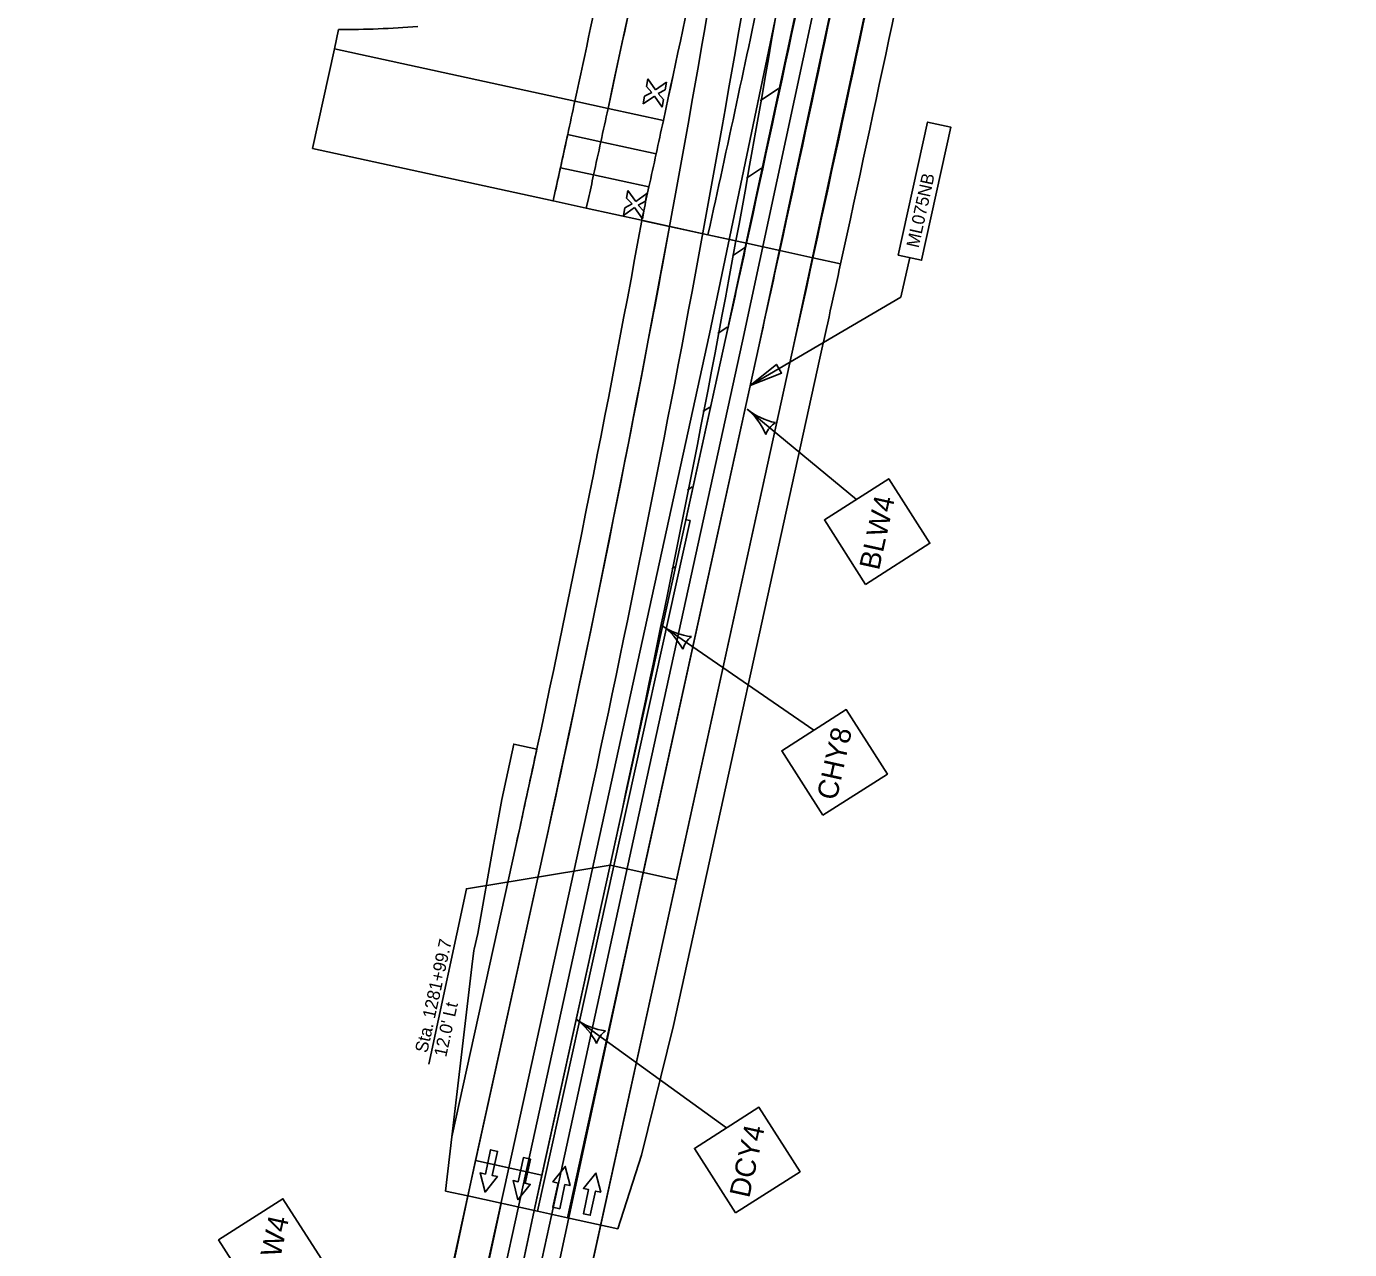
# Model space of a CAD drawing. Extents: x 14104283 to 14120882, y 8635219 to 8671666.
# Drawn here: x 14107625.7 to 14108093.2, y 8639045.1 to 8639477.1 of the extents above; entities that cross this region are included whole.
import ezdxf

# ---------------------------------------------------------------- set-up
doc = ezdxf.new("R2010")
doc.units = 0
for name, color, linetype in [('Cell', 7, 'Continuous'), ('dsnPaintExistingBrokenLaneLineWhite', 7, 'Continuous'), ('dsnPaintExistingEdgeLineRightWhite', 7, 'Continuous'), ('dsnPaintPlaceBrokenLaneWhite', 7, 'Continuous'), ('dsnPaintPlaceChannelizingLaneYellow', 7, 'Continuous'), ('dsnPaintPlaceDoubleCenterLineYellow', 7, 'Continuous'), ('dsnPaintPlaceEdgeLineRightWhite', 7, 'Continuous'), ('dsnPaintRemoveDoubleCenterLineYellow', 7, 'Continuous'), ('dsnPaintRemoveEdgeLineWhite', 7, 'Continuous'), ('dsnPaintRemoveEdgeLineYellow', 7, 'Continuous'), ('dsnShadingPaved', 7, 'Continuous'), ('dsnStdLabel', 7, 'Continuous'), ('dsnStgShadingPrevPav', 7, 'Continuous'), ('Text', 7, 'Continuous')]:
    doc.layers.add(name, color=color, linetype=linetype)

msp = doc.modelspace()

# ---------------------------------------------------------------- linework, layer by layer
at = {"layer": 'Cell'}
for p, q in [((14107845.2, 8639458.65), (14107844.72, 8639455.94)), ((14107847.94, 8639454.75), (14107845.2, 8639458.65)), ((14107851.85, 8639457.49), (14107847.94, 8639454.75)), ((14107851.37, 8639454.78), (14107851.85, 8639457.49)), ((14107843.65, 8639449.78), (14107847.55, 8639452.53)), ((14107844.12, 8639452.49), (14107843.65, 8639449.78)), ((14107846.64, 8639453.83), (14107844.12, 8639452.49)), ((14107844.72, 8639455.94), (14107846.64, 8639453.83)), ((14107847.55, 8639452.53), (14107850.3, 8639448.62)), ((14107848.86, 8639453.44), (14107851.37, 8639454.78)), ((14107850.77, 8639451.33), (14107848.86, 8639453.44)), ((14107850.3, 8639448.62), (14107850.77, 8639451.33)), ((14107838.22, 8639419.23), (14107837.75, 8639416.52)), ((14107837.75, 8639416.52), (14107839.66, 8639414.41)), ((14107840.97, 8639415.32), (14107838.22, 8639419.23)), ((14107844.87, 8639418.07), (14107840.97, 8639415.32)), ((14107841.88, 8639414.02), (14107844.4, 8639415.36)), ((14107844.4, 8639415.36), (14107844.87, 8639418.07)), ((14107836.67, 8639410.36), (14107840.58, 8639413.11)), ((14107837.15, 8639413.07), (14107836.67, 8639410.36)), ((14107839.66, 8639414.41), (14107837.15, 8639413.07)), ((14107840.58, 8639413.11), (14107843.32, 8639409.2)), ((14107843.8, 8639411.91), (14107841.88, 8639414.02)), ((14107843.32, 8639409.2), (14107843.8, 8639411.91))]:
    msp.add_line(p, q, dxfattribs=at)
for points in [[(14107789.7, 8639080.29), (14107792.14, 8639079.75), (14107790.27, 8639071.21), (14107792.11, 8639070.81), (14107787.72, 8639065.37), (14107786, 8639072.14), (14107787.83, 8639071.74)], [(14107801.31, 8639077.56), (14107803.75, 8639077.03), (14107801.89, 8639068.48), (14107803.72, 8639068.08), (14107799.34, 8639062.64), (14107797.61, 8639069.41), (14107799.45, 8639069.01)], [(14107814.11, 8639059.49), (14107811.66, 8639060.03), (14107813.53, 8639068.57), (14107811.7, 8639068.97), (14107816.08, 8639074.41), (14107817.8, 8639067.64), (14107815.97, 8639068.04)], [(14107824.92, 8639057.15), (14107822.48, 8639057.69), (14107824.34, 8639066.24), (14107822.51, 8639066.64), (14107826.89, 8639072.08), (14107828.62, 8639065.3), (14107826.78, 8639065.7)]]:
    msp.add_lwpolyline(points, close=True, dxfattribs=at)
for points in [[(14107787.83, 8639071.74), (14107786, 8639072.14), (14107787.72, 8639065.37), (14107792.11, 8639070.81), (14107790.27, 8639071.21), (14107792.14, 8639079.75), (14107789.7, 8639080.29), (14107787.83, 8639071.74)], [(14107799.45, 8639069.01), (14107797.61, 8639069.41), (14107799.34, 8639062.64), (14107803.72, 8639068.08), (14107801.89, 8639068.48), (14107803.75, 8639077.03), (14107801.31, 8639077.56), (14107799.45, 8639069.01)], [(14107815.97, 8639068.04), (14107817.8, 8639067.64), (14107816.08, 8639074.41), (14107811.7, 8639068.97), (14107813.53, 8639068.57), (14107811.66, 8639060.03), (14107814.11, 8639059.49), (14107815.97, 8639068.04)], [(14107826.78, 8639065.7), (14107828.62, 8639065.3), (14107826.89, 8639072.08), (14107822.51, 8639066.64), (14107824.34, 8639066.24), (14107822.48, 8639057.69), (14107824.92, 8639057.15), (14107826.78, 8639065.7)]]:
    msp.add_lwpolyline(points, dxfattribs=at)
at = {"layer": 'dsnPaintExistingBrokenLaneLineWhite'}
msp.add_line((14107796.13, 8639073.89), (14107820.2, 8639183.44), dxfattribs=at)
msp.add_arc((14101471.58, 8640578.08), 6500, 347.610212, 351.325989, dxfattribs=at)
at = {"layer": 'dsnPaintExistingEdgeLineRightWhite'}
for p, q in [((14107808.47, 8639186.01), (14107781.67, 8639064.01)), ((14107781.67, 8639064.01), (14107752.01, 8638929.68))]:
    msp.add_line(p, q, dxfattribs=at)
msp.add_arc((14101471.58, 8640578.08), 6488, 347.610212, 351.325989, dxfattribs=at)
at = {"layer": 'dsnPaintPlaceBrokenLaneWhite'}
for p, q in [((14107786.39, 8638912.75), (14107843.64, 8639178.29)), ((14107762.69, 8638916.73), (14107793.38, 8639061.35))]:
    msp.add_line(p, q, dxfattribs=at)
msp.add_lwpolyline([(14107843.64, 8639178.31), (14107884.58, 8639364.68), (14107924.33, 8639550.14), (14107962.2, 8639735.99), (14107989.47, 8639873.39), (14108016.73, 8640010.79)], dxfattribs=at)
at = {"layer": 'dsnPaintPlaceChannelizingLaneYellow'}
for p, q in [((14107891.4, 8639455.15), (14107884.98, 8639450.86)), ((14107885.38, 8639427.06), (14107880.12, 8639423.54)), ((14107879.35, 8639398.97), (14107875.12, 8639396.14)), ((14107873.33, 8639370.88), (14107869.98, 8639368.64)), ((14107867.16, 8639342.69), (14107864.7, 8639341.05)), ((14107860.96, 8639314.49), (14107859.28, 8639313.36)), ((14107854.77, 8639286.28), (14107853.72, 8639285.58))]:
    msp.add_line(p, q, dxfattribs=at)
msp.add_lwpolyline([(14107831.92, 8639180.86), (14107872.85, 8639367.2), (14107898.55, 8639487.12)], dxfattribs=at)
for start, end in [(349.4681, 351.325989), (347.610212, 349.4681)]:
    msp.add_arc((14101471.58, 8640578.08), 6512, start, end, dxfattribs=at)
at = {"layer": 'dsnPaintPlaceDoubleCenterLineYellow'}
for p in [(14107831.92, 8639180.86), (14107774.43, 8638914.24)]:
    msp.add_line(p, (14107805.11, 8639058.86), dxfattribs=at)
at = {"layer": 'dsnPaintPlaceEdgeLineRightWhite'}
msp.add_line((14107772.93, 8638800.49), (14107896.3, 8639362.11), dxfattribs=at)
msp.add_arc((14089678.7, 8643364.11), 18652, 347.610212, 348.776036, dxfattribs=at)
at = {"layer": 'dsnPaintRemoveDoubleCenterLineYellow'}
msp.add_line((14107796.13, 8639073.89), (14107763.69, 8638926.99), dxfattribs=at)
at = {"layer": 'dsnPaintRemoveEdgeLineWhite'}
msp.add_line((14107757.07, 8638810.81), (14107811.17, 8639057.08), dxfattribs=at)
msp.add_lwpolyline([(14107811.17, 8639057.08), (14107844.94, 8639211.53), (14107878.72, 8639365.97), (14107918.46, 8639551.34), (14107956.3, 8639737.1), (14108010.84, 8640011.94), (14108059.95, 8640246.87), (14108093.19, 8640398.18)], dxfattribs=at)
at = {"layer": 'dsnPaintRemoveEdgeLineYellow'}
msp.add_line((14107745.31, 8638813.23), (14107799.44, 8639059.65), dxfattribs=at)
msp.add_lwpolyline([(14107799.44, 8639059.65), (14107867, 8639368.55), (14107944.53, 8639739.44), (14107999.07, 8640014.27), (14108048.23, 8640249.45), (14108081.5, 8640400.87)], dxfattribs=at)
at = {"layer": 'dsnShadingPaved'}
for p, q in [((14107784.41, 8639076.47), (14107808.47, 8639186.01)), ((14107820.2, 8639183.44), (14107796.13, 8639073.89)), ((14107796.13, 8639073.89), (14107820.2, 8639183.44)), ((14107831.92, 8639180.86), (14107807.85, 8639071.32)), ((14107855.36, 8639175.71), (14107831.92, 8639180.86)), ((14107781.65, 8639063.92), (14107784.41, 8639076.47)), ((14107796.13, 8639073.89), (14107784.41, 8639076.47)), ((14107784.41, 8639076.47), (14107807.85, 8639071.32)), ((14107807.85, 8639071.32), (14107796.13, 8639073.89)), ((14107807.85, 8639071.32), (14107805.11, 8639058.86)), ((14107750.96, 8638919.22), (14107781.65, 8639063.92)), ((14107805.11, 8639058.86), (14107774.43, 8638914.24))]:
    msp.add_line(p, q, dxfattribs=at)
for points in [[(14107831.92, 8639180.86), (14107872.85, 8639367.2), (14107912.58, 8639552.57), (14107950.43, 8639738.33), (14108004.96, 8640013.11)], [(14108028.5, 8640008.43), (14107973.96, 8639733.6), (14107936.08, 8639547.66), (14107896.3, 8639362.11), (14107855.36, 8639175.71)]]:
    msp.add_lwpolyline(points, dxfattribs=at)
msp.add_lwpolyline([(14107649.12, 8638235.55), (14107625.69, 8638240.73), (14107678.53, 8638479.98), (14107744.48, 8638778.62), (14107774.43, 8638914.24), (14107805.11, 8639058.86), (14107831.92, 8639180.86), (14107855.36, 8639175.71), (14107834.62, 8639081.3), (14107772.93, 8638800.49), (14107710.93, 8638518.28), (14107648.94, 8638236.07)], close=True, dxfattribs=at)
for radius, start, end in [(6488, 347.610212, 351.325989), (6500, 347.610212, 351.325989), (6500, 347.610212, 351.325989), (6512, 349.4681, 351.325989), (6512, 347.610212, 349.4681)]:
    msp.add_arc((14101471.58, 8640578.08), radius, start, end, dxfattribs=at)
at = {"layer": 'dsnStdLabel'}
for p, q in [((14107919.02, 8639310.05), (14107880.3, 8639341.96)), ((14107903.96, 8639228.52), (14107850.2, 8639265.48)), ((14107873.1, 8639088.04), (14107819.95, 8639126.4))]:
    msp.add_line(p, q, dxfattribs=at)
for points in [[(14107922.2, 8639280.03), (14107944.94, 8639294.58), (14107930.39, 8639317.33), (14107907.65, 8639302.78)], [(14107907.14, 8639198.51), (14107929.88, 8639213.05), (14107915.33, 8639235.8), (14107892.59, 8639221.25)], [(14107876.27, 8639058.02), (14107899.02, 8639072.57), (14107884.47, 8639095.32), (14107861.72, 8639080.77)], [(14107708.11, 8639025.7), (14107730.86, 8639040.25), (14107716.31, 8639063), (14107693.56, 8639048.45)]]:
    msp.add_lwpolyline(points, close=True, dxfattribs=at)
for centre, radius, start, end in [((14107865.71, 8639324.25), 22.95, 22.4366, 50.5079), ((14107894.9, 8639359.67), 22.95, 230.5078, 258.579), ((14107895.15, 8639329.72), 8.86, 122.7736, 158.2421), ((14107837.2, 8639246.56), 22.95, 27.4258, 55.4971), ((14107863.2, 8639284.39), 22.95, 235.4969, 263.5682), ((14107866.06, 8639254.58), 8.86, 127.7628, 163.2312), ((14107806.52, 8639107.79), 22.95, 26.1067, 54.178), ((14107833.38, 8639145.01), 22.95, 234.1779, 262.2491), ((14107835.55, 8639115.14), 8.86, 126.4437, 161.9122)]:
    msp.add_arc(centre, radius, start, end, dxfattribs=at)
at = {"layer": 'dsnStgShadingPrevPav'}
for p, q in [((14107819.46, 8639450.69), (14107831.19, 8639448.13)), ((14107831.19, 8639448.13), (14107819.46, 8639450.69)), ((14107831.19, 8639448.13), (14107850.73, 8639443.87)), ((14107850.74, 8639443.87), (14107831.2, 8639448.13)), ((14107828.65, 8639436.4), (14107816.92, 8639438.96)), ((14107816.92, 8639438.96), (14107828.65, 8639436.4)), ((14107828.65, 8639436.4), (14107848.19, 8639432.14)), ((14107848.19, 8639432.14), (14107828.65, 8639436.4)), ((14107826.09, 8639424.68), (14107814.36, 8639427.23)), ((14107814.36, 8639427.23), (14107826.09, 8639424.68)), ((14107826.09, 8639424.68), (14107845.63, 8639420.42)), ((14107845.63, 8639420.42), (14107826.09, 8639424.68)), ((14107843.14, 8639408.63), (14107852.92, 8639406.48)), ((14107866.49, 8639403.5), (14107852.92, 8639406.48)), ((14107880.14, 8639400.54), (14107866.49, 8639403.51)), ((14107866.49, 8639403.51), (14107866.49, 8639403.5)), ((14107891.87, 8639397.99), (14107880.14, 8639400.54)), ((14107891.86, 8639397.97), (14107880.14, 8639400.52)), ((14107891.86, 8639397.97), (14107903.59, 8639395.42)), ((14107891.86, 8639397.97), (14107903.59, 8639395.42)), ((14107903.59, 8639395.44), (14107913.36, 8639393.31)), ((14107903.59, 8639395.44), (14107913.36, 8639393.31)), ((14107816.84, 8639056.28), (14107884.58, 8639364.69)), ((14107816.84, 8639056.28), (14107884.58, 8639364.69)), ((14107858.72, 8639302.86), (14107872.86, 8639367.26)), ((14107872.86, 8639367.26), (14107858.72, 8639302.86)), ((14107906.07, 8639359.97), (14107854.27, 8639124.15)), ((14107860.16, 8639302.55), (14107858.72, 8639302.86)), ((14107858.81, 8639302.85), (14107860.17, 8639302.55)), ((14107806.3, 8639058.6), (14107860.16, 8639302.55)), ((14107860.17, 8639302.55), (14107806.31, 8639058.6)), ((14107808.47, 8639186.01), (14107781.67, 8639064.01)), ((14107854.27, 8639124.15), (14107843.05, 8639078.38)), ((14107843.05, 8639078.38), (14107834.68, 8639052.36)), ((14107781.67, 8639064.01), (14107806.3, 8639058.6)), ((14107806.31, 8639058.6), (14107816.84, 8639056.28)), ((14107834.68, 8639052.36), (14107816.84, 8639056.28))]:
    msp.add_line(p, q, dxfattribs=at)
for points in [[(14107819.46, 8639450.69), (14107734.48, 8639469.22), (14107735.97, 8639476.04)], [(14107812.54, 8639418.89), (14107811.79, 8639415.51), (14107726.81, 8639434.04), (14107734.48, 8639469.22), (14107819.46, 8639450.69)], [(14107824.26, 8639416.31), (14107823.51, 8639412.94), (14107811.79, 8639415.51), (14107812.54, 8639418.89)], [(14107843.79, 8639412.02), (14107843.05, 8639408.65), (14107823.51, 8639412.94), (14107824.26, 8639416.31)], [(14107867.23, 8639406.87), (14107866.49, 8639403.51), (14107876.38, 8639401.36), (14107866.49, 8639403.5), (14107843.05, 8639408.65), (14107843.79, 8639412.02)], [(14107867.23, 8639406.87), (14107866.49, 8639403.51), (14107880.14, 8639400.54)], [(14107798.71, 8639188.16), (14107776.02, 8639084.89), (14107783.02, 8639144.91), (14107783.81, 8639150.65), (14107783.9, 8639151.14), (14107785.2, 8639156.75), (14107790.77, 8639188.01), (14107791.75, 8639193.68), (14107793.6, 8639204.06), (14107797.89, 8639223.6), (14107806.01, 8639221.81)], [(14107808.47, 8639186.01), (14107781.67, 8639064.01), (14107773.79, 8639065.74), (14107776.02, 8639084.89), (14107798.71, 8639188.16)]]:
    msp.add_lwpolyline(points, dxfattribs=at)
for centre, radius, start, end in [((14098576.76, 8641447.78), 9468, 347.807255, 351.672846), ((14089678.7, 8643364.11), 18628, 347.714997, 348.776036), ((14089678.7, 8643364.11), 18628, 347.714933, 348.776036), ((14089678.7, 8643364.11), 18640, 347.714933, 348.776036), ((14089678.7, 8643364.11), 18640, 347.714933, 348.776036), ((14089678.7, 8643364.11), 18662, 347.714933, 348.776036), ((14098576.76, 8641447.78), 9456, 347.807393, 348.449343), ((14098576.76, 8641447.78), 9456, 347.807393, 348.449343), ((14098576.77, 8641447.78), 9468, 347.807255, 348.194582), ((14098576.76, 8641447.78), 9488, 347.807026, 348.202524), ((14098576.77, 8641447.78), 9488, 347.807026, 348.202524), ((14098576.76, 8641447.78), 9512, 347.610212, 348.176197), ((14098576.76, 8641447.78), 9512, 347.610212, 348.176197), ((14107737.69, 8639796.04), 320, 269.6918, 274.7091), ((14098576.76, 8641447.78), 9456, 347.734683, 347.807393), ((14098576.76, 8641447.78), 9456, 347.734683, 347.807393), ((14098576.76, 8641447.78), 9468, 347.734637, 347.807255), ((14098576.76, 8641447.78), 9468, 347.734637, 347.807255), ((14098576.76, 8641447.78), 9488, 347.662095, 347.807026), ((14098576.76, 8641447.78), 9488, 347.73456, 347.807026), ((14098576.76, 8641447.78), 9456, 347.610212, 347.734683), ((14098576.76, 8641447.78), 9456, 347.661973, 347.734683), ((14098576.76, 8641447.78), 9468, 347.662019, 347.734637), ((14098576.76, 8641447.78), 9468, 347.662019, 347.734637), ((14098576.76, 8641447.78), 9488, 347.662095, 347.73456), ((14098576.76, 8641447.78), 9456, 347.610212, 347.661973), ((14098576.76, 8641447.78), 9468, 347.610212, 347.662019), ((14098576.76, 8641447.78), 9468, 347.610212, 347.662019), ((14098576.76, 8641447.78), 9488, 347.610212, 347.662095), ((14098576.76, 8641447.78), 9488, 347.610212, 347.662095), ((14101471.58, 8640578.08), 6478, 347.610212, 349.599496), ((14101471.57, 8640578.08), 6488, 347.610212, 349.596428), ((14101471.58, 8640578.08), 6488, 347.610212, 349.596429), ((14089678.7, 8643364.11), 18628, 347.610212, 347.714997), ((14089678.7, 8643364.11), 18628, 347.610212, 347.714997), ((14089678.7, 8643364.11), 18640, 347.610212, 347.714997), ((14089678.7, 8643364.11), 18640, 347.610212, 347.714933), ((14089678.7, 8643364.11), 18662, 347.610212, 347.714933), ((14101471.58, 8640578.08), 6478, 347.610212, 347.888031), ((14101471.58, 8640578.08), 6478, 347.888031, 347.914808)]:
    msp.add_arc(centre, radius, start, end, dxfattribs=at)
at = {"layer": 'Text'}
for points in [[(14107933.75, 8639396.36), (14107944.08, 8639443.35), (14107952.28, 8639441.55), (14107941.96, 8639394.56)], [(14107933.75, 8639396.36), (14107944.08, 8639443.35), (14107952.28, 8639441.55), (14107941.96, 8639394.56)], [(14107881.41, 8639350.25), (14107890.71, 8639357.76), (14107892.5, 8639354.7)]]:
    msp.add_lwpolyline(points, close=True, dxfattribs=at)
for points in [[(14107937.86, 8639395.46), (14107934.7, 8639381.51), (14107881.41, 8639350.25)], [(14107767.92, 8639110.53), (14107781.15, 8639172.54), (14107831.92, 8639180.86)]]:
    msp.add_lwpolyline(points, dxfattribs=at)

# ---------------------------------------------------------------- texts
at = {"layer": 'dsnStdLabel'}
for s, p in [('BLW4', (14107926.92, 8639284.77)), ('CHY8', (14107911.92, 8639203.49)), ('DCY4', (14107881.06, 8639063.03)), ('BLW4', (14107712.84, 8639030.44))]:
    msp.add_text(s, height=7.2, rotation=77.6078, dxfattribs=at).set_placement(p)
at = {"layer": 'Text'}
for s, height, p in [('ML075NB', 4.484, (14107940.92, 8639398.67)), ('Sta. 1281+99.7', 4.4845, (14107767.3, 8639114.31)), ("12.0' Lt", 4.484, (14107773.99, 8639112.84))]:
    msp.add_text(s, height=height, rotation=77.6078, dxfattribs=at).set_placement(p)

doc.saveas('drawing.dxf')
